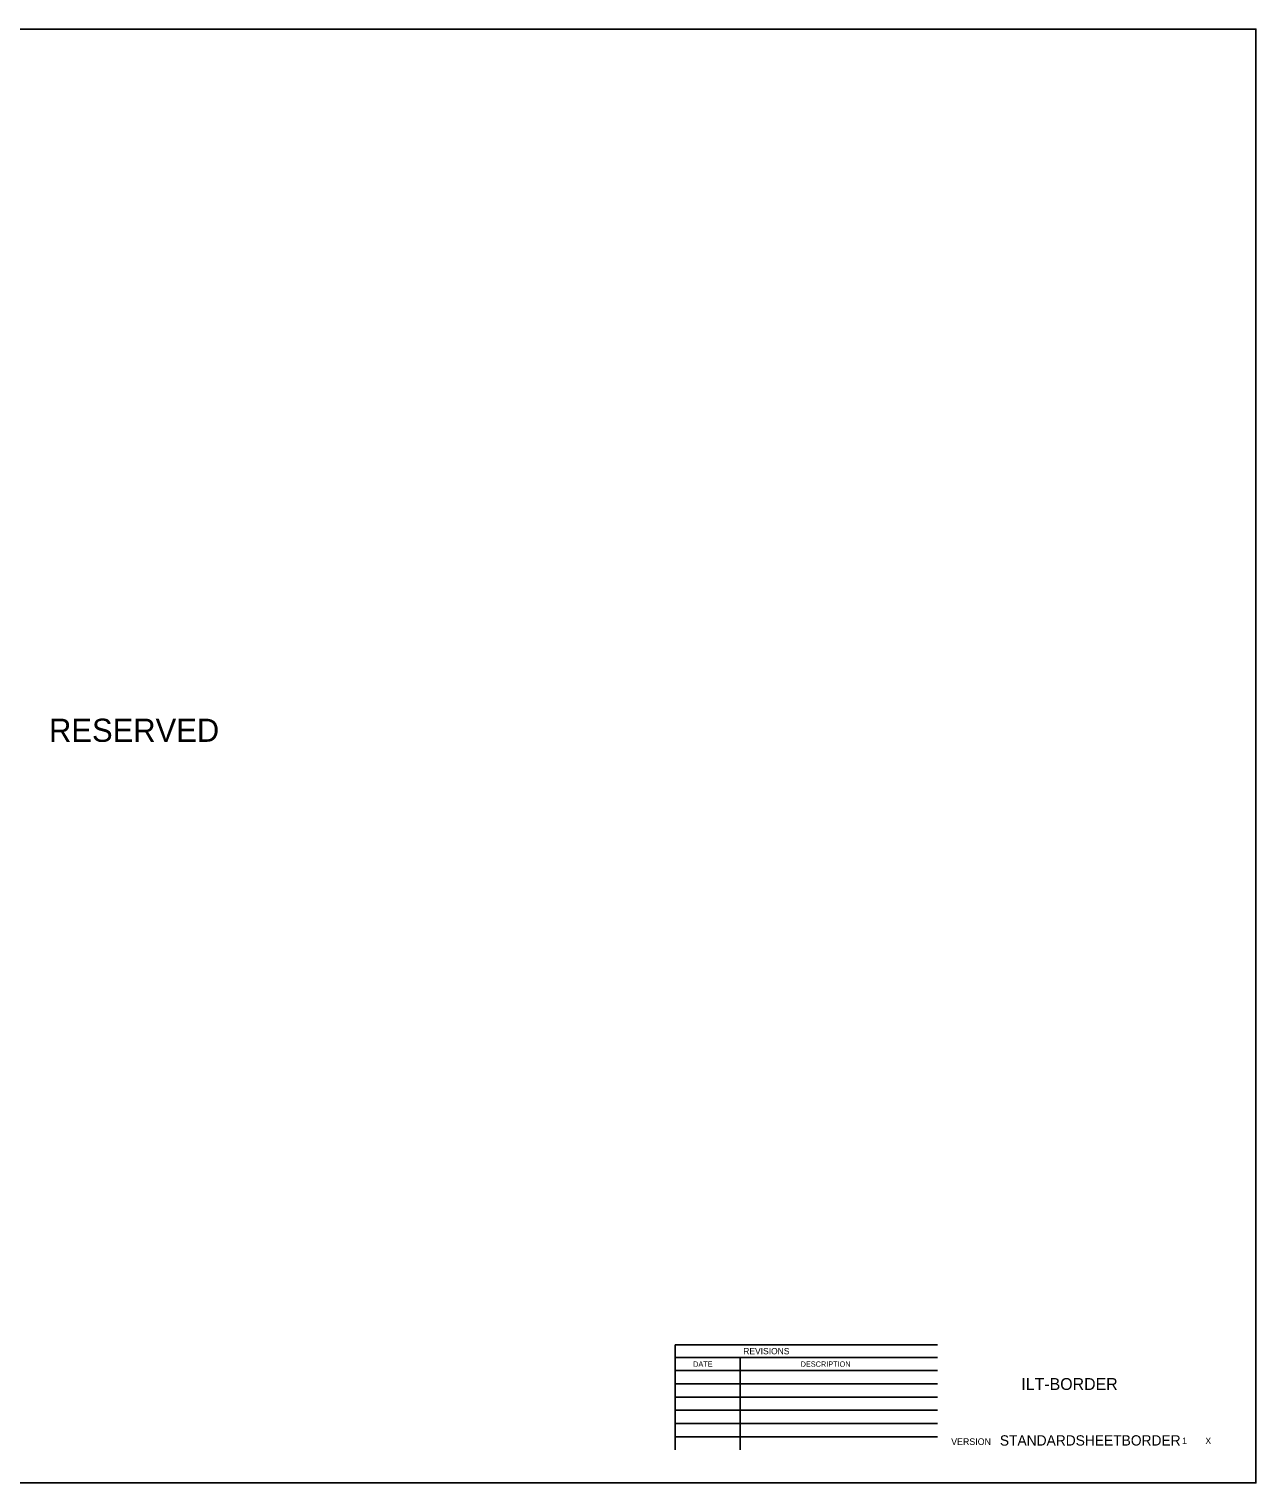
# Model space of a CAD drawing. Extents: x 0 to 2.83, y 0 to 1.83.
# Drawn here: x 1.286 to 2.833, y 0 to 1.833 of the extents above; entities that cross this region are included whole.
import ezdxf

# ---------------------------------------------------------------- set-up
doc = ezdxf.new("R2010")
doc.units = 0
for name, color, linetype in [('HS_Dimensions_and_Text', 7, 'Continuous'), ('SH_General_Details_Sheet_Number-ILTollway', 7, 'Continuous'), ('SH_General_Details_Sheet_Revision_Box-ILTollway', 7, 'Continuous'), ('SH_General_Details_Sheet_Standard-ILTollway', 7, 'Continuous'), ('SH_General_Details_Title_Text-ILTollway', 7, 'Continuous'), ('SH_General_Details_Total_Sheet_Number-ILTollway', 7, 'Continuous'), ('SH_General_Details_Version_Text-ILTollway', 7, 'Continuous'), ('SH_Printer Plotting Border-ILTollway', 7, 'Continuous')]:
    doc.layers.add(name, color=color, linetype=linetype)

msp = doc.modelspace()

# ---------------------------------------------------------------- linework, layer by layer
at = {"layer": 'SH_General_Details_Sheet_Revision_Box-ILTollway'}
for p, q in [((2.1008, 0.0417), (2.1008, 0.1743)), ((2.4317, 0.1743), (2.1008, 0.1743)), ((2.4317, 0.158), (2.1008, 0.158)), ((2.1827, 0.158), (2.1827, 0.0417)), ((2.4317, 0.1417), (2.1008, 0.1417)), ((2.4317, 0.125), (2.1008, 0.125)), ((2.4317, 0.1083), (2.1008, 0.1083)), ((2.4317, 0.0917), (2.1008, 0.0917)), ((2.4317, 0.075), (2.1008, 0.075)), ((2.4317, 0.0583), (2.1008, 0.0583))]:
    msp.add_line(p, q, dxfattribs=at)
at = {"layer": 'SH_Printer Plotting Border-ILTollway'}
msp.add_lwpolyline([(0, 1.8333), (2.8333, 1.8333), (2.8333, 0), (0, 0)], close=True, dxfattribs=at)

# ---------------------------------------------------------------- texts
at = {"layer": 'HS_Dimensions_and_Text'}
msp.add_text('RESERVED', height=0.02917, dxfattribs=at).set_placement((1.3113, 0.9345))
at = {"layer": 'SH_General_Details_Sheet_Number-ILTollway'}
msp.add_text('1', height=0.00833, rotation=0, dxfattribs=at).set_placement((2.7402, 0.0489))
at = {"layer": 'SH_General_Details_Sheet_Revision_Box-ILTollway'}
for s, height, p in [('REVISIONS', 0.008, (2.1868, 0.1622)), ('DATE', 0.00667, (2.1236, 0.1465)), ('DESCRIPTION', 0.006667, (2.2592, 0.1465))]:
    msp.add_text(s, height=height, rotation=0, dxfattribs=at).set_placement(p)
at = {"layer": 'SH_General_Details_Sheet_Standard-ILTollway'}
msp.add_text('STANDARDSHEETBORDER', height=0.013, dxfattribs=at).set_placement((2.5104, 0.0471))
at = {"layer": 'SH_General_Details_Title_Text-ILTollway'}
msp.add_text('ILT-BORDER', height=0.015, dxfattribs=at).set_placement((2.5375, 0.1172))
at = {"layer": 'SH_General_Details_Total_Sheet_Number-ILTollway'}
msp.add_text('X', height=0.00833, rotation=0, dxfattribs=at).set_placement((2.7695, 0.0489))
at = {"layer": 'SH_General_Details_Version_Text-ILTollway'}
msp.add_text('VERSION', height=0.00833, dxfattribs=at).set_placement((2.449, 0.0479))

doc.saveas('drawing.dxf')
